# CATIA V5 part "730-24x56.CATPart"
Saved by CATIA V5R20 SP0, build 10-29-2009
Part number: 730-24x56
Definition: NONE
Nomenclature: 730-24x56
Source: Unknown
Description: 730-24x56
Bounding box of the stored display mesh (mm): x -14.941 to 14.941, y -14.5 to 14.5, z 0 to 56
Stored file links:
  C:\Users\Utente\Desktop\IO LAVORO\3D X SITO CF\X SITO\730\730-24x56.CATPart
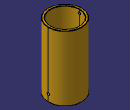
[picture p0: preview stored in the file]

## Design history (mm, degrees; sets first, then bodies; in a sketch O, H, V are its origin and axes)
Body1 "730-24x56" (main body)
  Solid1: solid without history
